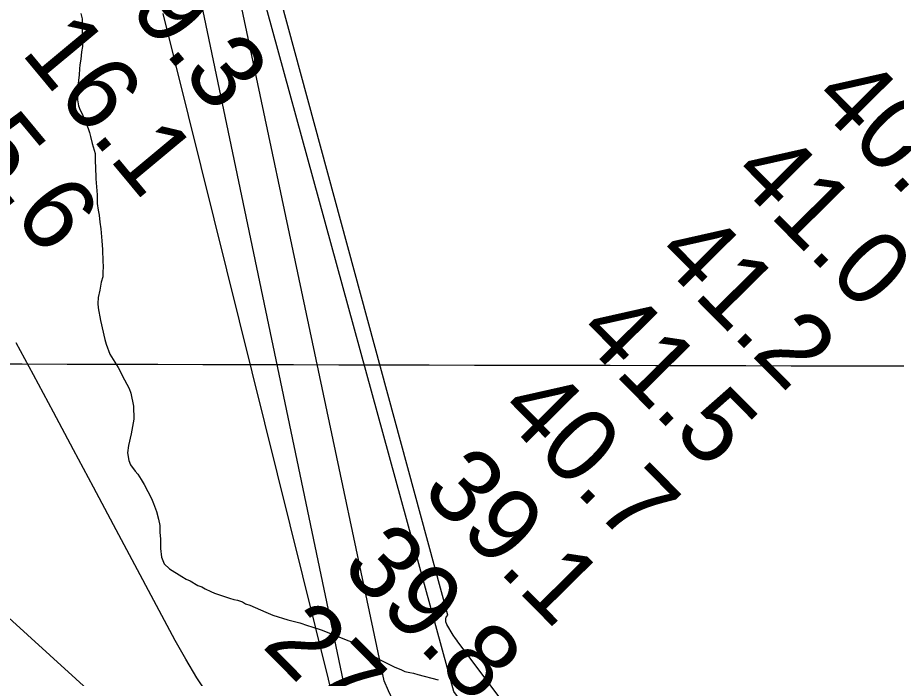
# Model space of a CAD drawing. Extents: x 3187622 to 3225504, y 800805 to 826213.
# Drawn here: x 3200246 to 3201041, y 818068 to 818665 of the extents above; entities that cross this region are included whole.
import ezdxf

# ---------------------------------------------------------------- set-up
doc = ezdxf.new("R2010")
doc.units = 0
for name, color, linetype in [('V-GRID-MAJR', 7, 'Continuous'), ('V-RIVR-RANG', 7, 'Continuous'), ('V-ROAD-CNTR', 7, 'Continuous'), ('V-SITE-VEGE', 7, 'Continuous'), ('V-TOPO-DPTH', 7, 'Continuous'), ('V-TOPO-MAJR', 7, 'Continuous'), ('V-TOPO-MINR', 7, 'Continuous'), ('V-TOPO-WATR', 7, 'Continuous')]:
    doc.layers.add(name, color=color, linetype=linetype)

msp = doc.modelspace()

# ---------------------------------------------------------------- linework, layer by layer
at = {"layer": 'V-GRID-MAJR'}
msp.add_spline([(3191823.839, 818371.837), (3197059.682, 818359.272), (3202295.526, 818347.468), (3207531.372, 818336.426), (3212767.22, 818326.145), (3218003.0700000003, 818316.626), (3223238.92, 818307.868), (3223238.921, 818307.868)], degree=3, dxfattribs=at)
at = {"layer": 'V-ROAD-CNTR'}
msp.add_spline([(3201024.1469147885, 823274.715423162), (3201018.0129270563, 823194.189584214), (3201004.718953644, 822963.7310451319), (3200987.4149882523, 822858.6972551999), (3200966.948029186, 822788.416395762), (3200937.8420873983, 822670.750631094), (3200879.4052042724, 822446.800078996), (3200861.238240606, 822331.312309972), (3200852.3482583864, 822205.904560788), (3200845.9832711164, 822103.0497664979), (3200850.494262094, 822002.651967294), (3200859.8182434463, 821900.4111717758), (3200873.148216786, 821709.08955442), (3200906.150150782, 821470.9180307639), (3200956.550049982, 821171.314629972), (3200981.83099942, 821020.504931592), (3201004.428954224, 820882.865206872), (3201024.90091328, 820767.6074373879), (3201030.704901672, 820687.434597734), (3201025.0879129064, 820574.7828230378), (3201019.728923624, 820485.638001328), (3201009.904943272, 820413.658145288), (3200981.8429993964, 820299.159374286), (3200938.6350858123, 820153.0996664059), (3200919.6651237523, 820054.1388643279), (3200905.8851513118, 819899.779173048), (3200911.078140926, 819808.036356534), (3200923.595115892, 819715.0165425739), (3200943.704075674, 819632.5057075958), (3200989.973983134, 819544.474883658), (3201077.634807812, 819388.707195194), (3201164.584633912, 819241.2794900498), (3201215.4495321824, 819169.23463414), (3201320.5073220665, 819031.1739102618), (3201438.252086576, 818874.583223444), (3201472.894017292, 818830.2363121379), (3201517.7899275, 818788.499395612), (3201613.6647357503, 818704.054564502), (3201703.731555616, 818596.021780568), (3201763.792435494, 818510.519951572), (3201836.136290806, 818397.89617682), (3201893.7711755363, 818288.104396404), (3201909.952143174, 818246.3284799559), (3201920.8531213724, 818198.082576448), (3201929.8091034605, 818155.84666092), (3201937.905087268, 818094.070784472), (3201957.718047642, 817998.595975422), (3201977.8520073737, 817926.3501199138), (3202055.382852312, 817776.5004196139), (3202147.001669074, 817623.97272467), (3202184.387594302, 817575.26282209), (3202228.252506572, 817509.5509535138), (3202265.871431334, 817464.9970426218), (3202335.4492921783, 817389.266194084), (3202595.371772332, 817156.054660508), (3202698.6155658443, 817066.2408401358), (3202845.2082726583, 816933.75410511), (3202967.1920286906, 816832.346307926), (3203084.1367948, 816744.1614842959), (3203205.803551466, 816662.3206479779), (3203334.4592941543, 816585.86980088), (3203420.0661229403, 816528.708915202), (3203529.074904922, 816448.4050758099), (3203624.28071451, 816386.379199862), (3203720.2955224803, 816332.45030772), (3203800.7433615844, 816304.608363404), (3203929.0741049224, 816241.273490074), (3204015.146932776, 816192.42558777), (3204112.488738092, 816105.381761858), (3204200.50956205, 816023.2659260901)], degree=3, dxfattribs=at)
at = {"layer": 'V-SITE-VEGE'}
for points in [[(3200303.381, 818668.73), (3200304.6410000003, 818663.888), (3200304.674, 818660.253), (3200305.112, 818656.62), (3200304.7430000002, 818652.974), (3200304.877, 818638.829), (3200304.115, 818633.971), (3200303.367, 818627.495), (3200302.607, 818622.234), (3200302.239, 818618.59), (3200301.882, 818613.331), (3200300.008, 818597.953), (3200300.481, 818590.682), (3200301.34, 818585.433), (3200302.994, 818581.405), (3200304.6410000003, 818578.188), (3200310.021, 818564.898), (3200311.268, 818561.2710000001), (3200312.112, 818557.642), (3200313.789, 818551.189), (3200316.3000000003, 818542.319), (3200316.376, 818534.235), (3200316.8140000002, 818530.6), (3200316.923, 818519.283), (3200318.272, 818504.742), (3200318.344, 818497.06), (3200319.21, 818491.006), (3200320.058, 818486.566), (3200320.525, 818480.103), (3200321.392, 818474.047), (3200322.303, 818463.1410000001), (3200323.184, 818455.4670000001), (3200323.288, 818444.5530000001), (3200323.73, 818440.517), (3200323.382, 818434.449), (3200323.417, 818430.813), (3200321.846, 818425.9450000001), (3200320.703, 818418.657), (3200319.147, 818412.1730000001), (3200318.7970000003, 818406.512), (3200319.235, 818402.877), (3200321.367, 818391.174), (3200325.164, 818374.231), (3200326.419, 818369.795), (3200329.737, 818360.934), (3200337.128, 818348.875), (3200342.894, 818337.611), (3200347.0100000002, 818329.97), (3200348.669, 818325.5380000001), (3200351.204, 818313.838), (3200351.315, 818302.115), (3200349.017, 818288.7540000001), (3200346.691, 818278.219), (3200345.537, 818271.741), (3200346.815, 818264.882), (3200348.47, 818260.854), (3200352.566, 818255.234), (3200355.02, 818252.424), (3200357.893, 818247.603), (3200360.7660000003, 818243.184), (3200367.357, 818230.308), (3200369.0160000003, 818225.878), (3200371.914, 818218.628), (3200373.595, 818211.772), (3200374.861, 818206.125), (3200374.918, 818200.059), (3200375.383, 818193.598), (3200375.465, 818185.109), (3200376.346, 818177.437), (3200378.828, 818171.395), (3200383.72, 818166.9940000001), (3200394.704, 818159.822), (3200398.767, 818157.434), (3200402.423, 818155.853), (3200409.333, 818151.876), (3200412.982, 818150.696), (3200415.8310000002, 818148.703), (3200421.109, 818146.328), (3200424.357, 818144.741), (3200437.738, 818140.421)], [(3200437.738, 818140.421), (3200441.791, 818139.246), (3200445.0330000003, 818138.468), (3200449.4960000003, 818136.895), (3200452.341, 818135.3030000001), (3200456.394, 818134.13), (3200470.603, 818127.795), (3200477.097, 818125.027), (3200490.4790000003, 818120.7050000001), (3200501.419, 818117.979), (3200508.315, 818115.62), (3200512.3680000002, 818114.4450000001), (3200520.883, 818111.696), (3200545.6350000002, 818101.823), (3200549.285, 818100.645), (3200552.943, 818098.659), (3200557.012, 818095.8690000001), (3200563.117, 818091.478), (3200568.407, 818087.888), (3200572.063, 818085.904), (3200575.3170000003, 818083.9130000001), (3200578.969, 818082.328), (3200587.501, 818077.964), (3200592.774, 818075.991), (3200596.432, 818074.005), (3200600.884, 818073.2390000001), (3200604.126, 818072.461), (3200608.179, 818071.287), (3200626.417, 818066.607)]]:
    msp.add_lwpolyline(points, dxfattribs=at)
at = {"layer": 'V-TOPO-DPTH'}
for points in [[(3201349.9629572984, 817080.6381240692), (3201062.6416491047, 817285.1742495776), (3201029.1550473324, 817309.8110769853), (3200996.2071972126, 817335.1268226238), (3200964.067474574, 817361.4609456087), (3200932.4665035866, 817388.4739868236), (3200881.8476434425, 817433.1336477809), (3200876.035336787, 817438.4040445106), (3200870.32186604, 817443.7767223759), (3200864.7566491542, 817449.3028219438), (3200859.290268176, 817454.9312026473), (3200550.1939602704, 817974.9718875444), (3200377.9527381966, 818668.8148178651)], [(3200144.0958271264, 818207.9765301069), (3200429.926489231, 817948.2173660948), (3200443.7843477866, 817935.088859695), (3200457.2619028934, 817921.5959059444), (3200470.169002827, 817907.556281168), (3200482.695799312, 817893.1522090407), (3200789.883120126, 817454.7108242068), (3200812.910268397, 817430.5607712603), (3200836.2354231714, 817406.7076946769), (3200860.0075877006, 817383.3000826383), (3200884.0777587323, 817360.1894469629), (3200971.9929042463, 817277.3628791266), (3201024.6007589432, 817228.5045793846), (3201077.665435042, 817180.1548996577)], [(3200144.0958271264, 818207.9765301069), (3200429.926489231, 817948.2173660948), (3200443.7843477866, 817935.088859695), (3200457.2619028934, 817921.5959059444), (3200470.169002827, 817907.556281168), (3200482.695799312, 817893.1522090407), (3200789.883120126, 817454.7108242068), (3200812.910268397, 817430.5607712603), (3200836.2354231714, 817406.7076946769), (3200860.0075877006, 817383.3000826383), (3200884.0777587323, 817360.1894469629), (3200971.9929042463, 817277.3628791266), (3201024.6007589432, 817228.5045793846), (3201077.665435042, 817180.1548996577)]]:
    msp.add_lwpolyline(points, dxfattribs=at)
at = {"layer": 'V-TOPO-MAJR'}
msp.add_lwpolyline([(3201092.9302284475, 817506.2196689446), (3201017.309746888, 817575.7357708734), (3201010.535226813, 817582.1855841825), (3201003.9172085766, 817588.7869045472), (3200997.5339430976, 817595.6154854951), (3200991.307179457, 817602.5955734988), (3200923.003693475, 817681.9118788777), (3200891.482152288, 817719.4898341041), (3200860.6256728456, 817757.592255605), (3200830.766786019, 817796.481376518), (3200801.5729609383, 817835.8949637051), (3200772.8189856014, 817875.6590058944), (3200743.9853821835, 817915.3650406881), (3200715.032336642, 817954.9840643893), (3200685.9996630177, 817994.5450806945), (3200640.7920922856, 818055.9525572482), (3200466.289368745, 818692.6503982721)], dxfattribs=at)
at = {"layer": 'V-TOPO-MINR'}
for points in [[(3201477.5177741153, 817239.3970811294), (3201031.08176724, 817590.6886283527), (3201028.6660940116, 817592.6686129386), (3201026.3058257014, 817594.7101340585), (3201024.0286647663, 817596.8439599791), (3201021.806908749, 817599.0393224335), (3201019.704836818, 817601.3423056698), (3201017.7057799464, 817603.7262697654), (3200644.43974432, 818100.8680965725), (3200643.293832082, 818102.2968390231), (3200642.195141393, 818103.7593289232), (3200640.1866462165, 818106.8192985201), (3200634.2592988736, 818116.6809283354), (3200633.384687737, 818118.8110032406), (3200633.4143264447, 818122.2103573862), (3200633.813083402, 818123.2200850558), (3200635.291802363, 818124.8572084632), (3200472.4159130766, 818724.552140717)], [(3201395.0167852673, 817158.4609795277), (3201061.252619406, 817439.3937593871), (3201043.123074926, 817454.9788201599), (3201025.2157577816, 817470.8100407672), (3201007.641781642, 817487.0105011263), (3200990.290032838, 817503.4571213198), (3200973.2603789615, 817520.2395730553), (3200956.437577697, 817537.2232406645), (3200939.9250553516, 817554.5087320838), (3200923.6193856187, 817571.9954393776), (3200921.1083736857, 817574.7376950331), (3200903.8909131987, 817593.9083129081), (3200886.924514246, 817613.2944206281), (3200870.334707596, 817633.0037631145), (3200853.9959624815, 817652.9285954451), (3200571.5468947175, 818004.2188340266), (3200564.9232412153, 818012.7131134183), (3200558.4727459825, 818021.3329906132), (3200552.28198815, 818030.1412645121), (3200546.264388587, 818039.075136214), (3200407.1894124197, 818704.4374990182)], [(3201322.5587361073, 817268.2575497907), (3201018.3586623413, 817549.1243726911), (3201004.7745844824, 817562.04846244), (3200991.457505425, 817575.2342588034), (3200978.5409245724, 817588.8126150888), (3200965.8913425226, 817602.6526779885), (3200650.7364019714, 817958.004951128), (3200642.924407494, 817966.9789907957), (3200635.224955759, 817976.0468149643), (3200627.694318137, 817985.2553158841), (3200620.2762232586, 817994.5576013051), (3200617.8070225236, 817997.7133447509), (3200611.8612443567, 818005.6133182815), (3200606.1191257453, 818013.6530573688), (3200600.682496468, 818021.9024447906), (3200595.4495267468, 818030.2915977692), (3200590.5649126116, 818038.8839456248), (3200585.9392845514, 818047.6064137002), (3200581.7021356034, 818056.5240621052), (3200577.7239727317, 818065.57183073), (3200448.1822112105, 818677.9129323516)], [(3201349.9629572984, 817080.6381240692), (3201062.6416491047, 817285.1742495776), (3201029.1550473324, 817309.8110769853), (3200996.2071972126, 817335.1268226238), (3200964.067474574, 817361.4609456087), (3200932.4665035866, 817388.4739868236), (3200881.8476434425, 817433.1336477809), (3200876.035336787, 817438.4040445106), (3200870.32186604, 817443.7767223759), (3200864.7566491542, 817449.3028219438), (3200859.290268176, 817454.9312026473), (3200550.1939602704, 817974.9718875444), (3200377.9527381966, 818668.8148178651)], [(3201256.6442505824, 817052.1544862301), (3200882.9935799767, 817397.9320824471), (3200868.3156804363, 817411.7912077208), (3200853.8277889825, 817425.8423519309), (3200839.6249096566, 817440.1815245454), (3200492.000501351, 817957.9747626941), (3200482.343501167, 817969.7549991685), (3200472.52163654, 817981.4029308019), (3200462.732325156, 817993.0747393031), (3200453.1511195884, 818004.9105624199), (3200443.882072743, 818016.99240746), (3200434.821131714, 818029.2382671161), (3200429.8638764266, 818036.1242031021), (3200408.2106757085, 818068.4411144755), (3200398.27268879, 818085.1525930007), (3200388.7790085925, 818102.1405829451), (3200333.0972784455, 818206.6816713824), (3200315.002185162, 818240.6089665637), (3200296.881779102, 818274.5227186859), (3200278.723403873, 818308.41615622), (3200260.5397158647, 818342.296050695), (3200245.112334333, 818371.0017999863)]]:
    msp.add_lwpolyline(points, dxfattribs=at)
at = {"layer": 'V-TOPO-WATR'}
msp.add_lwpolyline([(3201077.665435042, 817180.1548996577), (3201024.6007589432, 817228.5045793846), (3200971.9929042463, 817277.3628791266), (3200884.0777587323, 817360.1894469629), (3200860.0075877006, 817383.3000826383), (3200836.2354231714, 817406.7076946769), (3200812.910268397, 817430.5607712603), (3200789.883120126, 817454.7108242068), (3200482.695799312, 817893.1522090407), (3200470.169002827, 817907.556281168), (3200457.2619028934, 817921.5959059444), (3200443.7843477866, 817935.088859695), (3200429.926489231, 817948.2173660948), (3200144.0958271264, 818207.9765301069)], dxfattribs=at)

# ---------------------------------------------------------------- texts
at = {"layer": 'V-RIVR-RANG'}
for s, rotation, p in [('19.3', 309.76152777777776, (3200314.5295302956, 818710.3057449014)), ('16.1', 309.76152777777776, (3200248.490791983, 818633.3276432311)), ('40.5', 314.65832571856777, (3200963.1709703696, 818589.9217674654)), ('15.6', 309.76152777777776, (3200161.193377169, 818581.8986617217)), ('41.0', 314.65832571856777, (3200890.173518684, 818521.5226892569)), ('41.2', 314.65832571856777, (3200821.2549703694, 818448.9967674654)), ('41.5', 314.65832571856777, (3200750.2969703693, 818378.5337674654)), ('40.7', 314.65832571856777, (3200679.338970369, 818308.0717674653)), ('39.1', 314.65832571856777, (3200610.0496126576, 818235.9201041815)), ('39.8', 314.65832571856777, (3200537.4229703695, 818167.1467674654)), ('27.9', 314.65832571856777, (3200466.279565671, 818096.8713967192))]:
    msp.add_text(s, height=67, rotation=rotation, dxfattribs=at).set_placement(p)

doc.saveas('drawing.dxf')
